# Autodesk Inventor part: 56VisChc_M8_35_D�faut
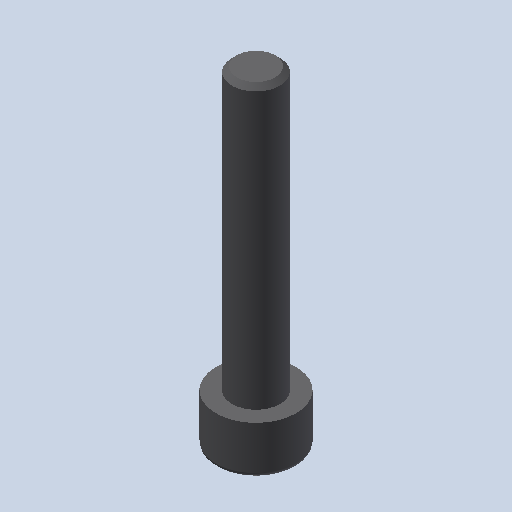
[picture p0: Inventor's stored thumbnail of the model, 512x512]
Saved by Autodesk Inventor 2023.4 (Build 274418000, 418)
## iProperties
Created: 2011-01
Part Number: 56VisChc_M8_35_D�faut
Document SubType Name: Modeling
Designer: eric
Density: 1 g/cm^3
Mass: 1.39036 g
Surface Area: 10.4193 cm^2
Volume: 1.39036 cm^3
Material: Générique
Appearance: Red
Author: eric
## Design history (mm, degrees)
feature "Base1"
node "Corps solides"
node "Corps surfaciques"
node "Solide1"
